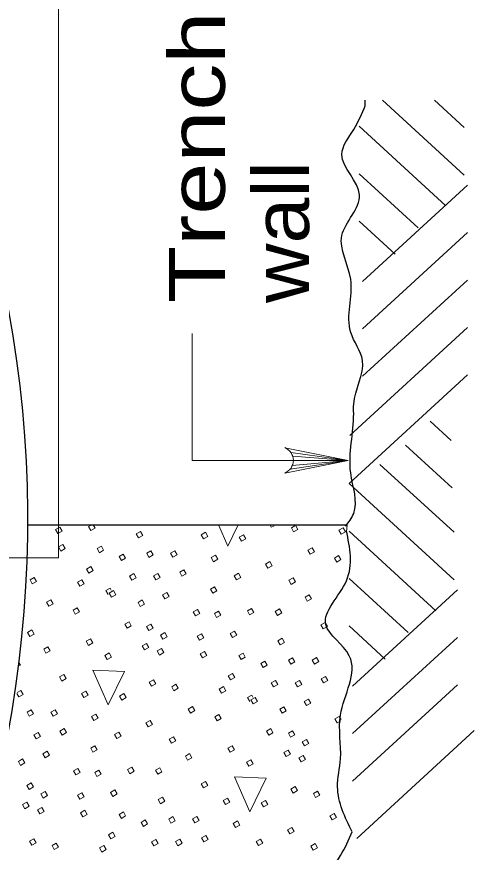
# Model space of a CAD drawing. Extents: x 1170.6 to 1204.6, y 975 to 1019.
# Drawn here: x 1195.183 to 1196.459, y 1001.839 to 1004.167 of the extents above; entities that cross this region are included whole.
import ezdxf

# ---------------------------------------------------------------- set-up
doc = ezdxf.new("R2010")
doc.units = 0
doc.header["$LTSCALE"] = 0.062
doc.linetypes.add('LONG_DASHED', pattern=[7.5, 6, -1.5])
doc.layers.add('1', color=7, linetype='Continuous', lineweight=13)

msp = doc.modelspace()

# ---------------------------------------------------------------- linework, layer by layer
at = {"layer": '1', "lineweight": 25}
for p, q in [((1196.155, 1003.91933), (1196.15475, 1003.93433)), ((1195.21267, 1002.7515), (1196.10433, 1002.7515))]:
    msp.add_line(p, q, dxfattribs=at)
at = {"layer": '1'}
for p, q in [((1196.20317, 1003.93433), (1196.43025, 1003.72617)), ((1196.34742, 1003.93433), (1196.43025, 1003.85842)), ((1196.13792, 1003.862), (1196.37983, 1003.64008)), ((1196.13792, 1003.72983), (1196.30225, 1003.57917)), ((1196.14733, 1003.43), (1196.43967, 1003.698)), ((1196.13792, 1003.59758), (1196.23842, 1003.50533)), ((1196.14733, 1003.29775), (1196.43967, 1003.56575)), ((1196.14733, 1003.16558), (1196.43967, 1003.43358)), ((1196.11175, 1003.00075), (1196.43967, 1003.30142)), ((1196.10992, 1002.86667), (1196.43967, 1003.16917)), ((1196.33558, 1003.04075), (1196.39458, 1002.98658)), ((1196.26725, 1002.97333), (1196.39667, 1002.85467)), ((1195.94717, 1002.95358), (1196.10742, 1002.93117)), ((1195.94533, 1002.90642), (1196.10742, 1002.93117)), ((1195.95142, 1002.91683), (1196.10742, 1002.93117)), ((1195.95267, 1002.9425), (1196.10742, 1002.93117)), ((1195.95425, 1002.93117), (1196.10742, 1002.93117)), ((1196.05575, 1002.93117), (1196.10742, 1002.93117)), ((1196.19575, 1002.92008), (1196.40225, 1002.73083)), ((1196.10992, 1002.86667), (1196.40225, 1002.59858)), ((1195.38358, 1002.74658), (1195.39267, 1002.75183)), ((1195.94892, 1002.74342), (1195.95825, 1002.74875)), ((1196.10225, 1002.73192), (1196.10433, 1002.7515)), ((1196.10992, 1002.73442), (1196.35183, 1002.5125)), ((1196.10992, 1002.60225), (1196.27425, 1002.45158)), ((1195.438, 1002.5575), (1195.43183, 1002.56842)), ((1196.11933, 1002.30242), (1196.41167, 1002.57042)), ((1196.10992, 1002.47), (1196.21042, 1002.37775)), ((1196.11933, 1002.17017), (1196.41167, 1002.43817)), ((1196.11933, 1002.03792), (1196.41167, 1002.306)), ((1195.83283, 1002.25992), (1195.82675, 1002.27083)), ((1196.13092, 1001.87817), (1196.45875, 1002.17883))]:
    msp.add_line(p, q, dxfattribs=at)
for points in [[(1194.2025, 1003.9905), (1194.2025, 1004.66792), (1195.30008, 1004.66792), (1195.30008, 1002.65925), (1194.2025, 1002.65925), (1194.2025, 1002.74183)], [(1196.10742, 1002.93117), (1195.67233, 1002.93117), (1195.67233, 1003.28433)], [(1195.93042, 1002.89583), (1196.10742, 1002.93117), (1195.93042, 1002.96658)], [(1195.39633, 1002.75175), (1195.40175, 1002.74208), (1195.38992, 1002.73542), (1195.38358, 1002.74658)], [(1195.74625, 1002.74992), (1195.77133, 1002.69242), (1195.79917, 1002.74958)], [(1195.90058, 1002.74908), (1195.89275, 1002.74467), (1195.89025, 1002.74917)], [(1195.9615, 1002.74875), (1195.96708, 1002.73892), (1195.95525, 1002.73217), (1195.94892, 1002.74342)], [(1195.43183, 1002.56842), (1195.44375, 1002.57508), (1195.44692, 1002.56942)], [(1195.19017, 1002.36658), (1195.19342, 1002.36092), (1195.18958, 1002.35883)], [(1195.18417, 1002.2845), (1195.1945, 1002.29033), (1195.20083, 1002.27908), (1195.189, 1002.27242), (1195.18392, 1002.28133)], [(1195.82675, 1002.27083), (1195.83858, 1002.2775), (1195.84183, 1002.27183)], [(1196.07042, 1002.21133), (1196.08225, 1002.21808), (1196.08733, 1002.209)], [(1196.08708, 1002.20592), (1196.07675, 1002.20008), (1196.07042, 1002.21133)]]:
    msp.add_lwpolyline(points, dxfattribs=at)
for points in [[(1195.29167, 1002.73883), (1195.3035, 1002.7455), (1195.30983, 1002.73425), (1195.298, 1002.72758)], [(1196.08125, 1002.73683), (1196.09308, 1002.74358), (1196.09942, 1002.73233), (1196.08758, 1002.72558)], [(1195.51625, 1002.72633), (1195.52808, 1002.733), (1195.53442, 1002.72175), (1195.52258, 1002.71508)], [(1195.69758, 1002.72408), (1195.70942, 1002.73083), (1195.71575, 1002.71958), (1195.70392, 1002.71283)], [(1195.80342, 1002.71742), (1195.81525, 1002.72408), (1195.82158, 1002.71283), (1195.80975, 1002.70617)], [(1195.30008, 1002.68992), (1195.31192, 1002.69667), (1195.31825, 1002.68542), (1195.30642, 1002.67867)], [(1195.40733, 1002.68533), (1195.41917, 1002.692), (1195.4255, 1002.68075), (1195.41367, 1002.67408)], [(1195.46858, 1002.66308), (1195.48042, 1002.66975), (1195.48675, 1002.6585), (1195.47492, 1002.65183)], [(1195.54567, 1002.67225), (1195.5575, 1002.67892), (1195.56383, 1002.66767), (1195.552, 1002.661)], [(1195.61233, 1002.67258), (1195.62417, 1002.67925), (1195.63058, 1002.66808), (1195.61867, 1002.66133)], [(1195.995, 1002.68117), (1196.00683, 1002.68792), (1196.01317, 1002.67667), (1196.00133, 1002.66992)], [(1195.72533, 1002.66017), (1195.73717, 1002.66683), (1195.7435, 1002.65558), (1195.73167, 1002.64892)], [(1195.87708, 1002.64233), (1195.88892, 1002.64908), (1195.89525, 1002.63783), (1195.88342, 1002.63108)], [(1196.06883, 1002.65917), (1196.08067, 1002.66592), (1196.087, 1002.65467), (1196.07517, 1002.64792)], [(1195.37792, 1002.6285), (1195.38975, 1002.63525), (1195.39608, 1002.624), (1195.38425, 1002.61733)], [(1195.6375, 1002.61992), (1195.64933, 1002.62667), (1195.65567, 1002.61542), (1195.64383, 1002.60867)], [(1195.22042, 1002.59833), (1195.23225, 1002.605), (1195.23858, 1002.59375), (1195.22675, 1002.58708)], [(1195.498, 1002.609), (1195.50983, 1002.61567), (1195.51617, 1002.60442), (1195.50433, 1002.59775)], [(1195.56467, 1002.60933), (1195.5765, 1002.616), (1195.58283, 1002.60475), (1195.571, 1002.59808)], [(1195.78975, 1002.60983), (1195.80158, 1002.61658), (1195.80792, 1002.60533), (1195.79608, 1002.59858)], [(1195.94208, 1002.59708), (1195.95392, 1002.60375), (1195.96025, 1002.5925), (1195.94842, 1002.58583)], [(1195.35275, 1002.59167), (1195.36458, 1002.59842), (1195.37092, 1002.58717), (1195.35908, 1002.58042)], [(1195.72317, 1002.57217), (1195.735, 1002.57892), (1195.74133, 1002.56767), (1195.7295, 1002.56092)], [(1195.441, 1002.5615), (1195.45283, 1002.56825), (1195.45917, 1002.557), (1195.44733, 1002.55025)], [(1195.58983, 1002.55667), (1195.60167, 1002.56342), (1195.608, 1002.55217), (1195.59617, 1002.54542)], [(1195.987, 1002.55017), (1195.99883, 1002.55683), (1196.00517, 1002.54558), (1195.99333, 1002.53892)], [(1195.2665, 1002.536), (1195.27833, 1002.54275), (1195.28467, 1002.5315), (1195.27283, 1002.52483)], [(1195.5215, 1002.5355), (1195.53333, 1002.54225), (1195.53967, 1002.531), (1195.52783, 1002.52425)], [(1195.34033, 1002.51408), (1195.35217, 1002.52075), (1195.3585, 1002.50958), (1195.34667, 1002.50283)], [(1195.6755, 1002.50892), (1195.68733, 1002.51567), (1195.69367, 1002.50442), (1195.68183, 1002.49767)], [(1195.73425, 1002.5045), (1195.74608, 1002.51125), (1195.75242, 1002.5), (1195.74058, 1002.49325)], [(1195.82617, 1002.51233), (1195.838, 1002.519), (1195.84433, 1002.50775), (1195.8325, 1002.50108)], [(1195.90367, 1002.51058), (1195.9155, 1002.51733), (1195.92192, 1002.50608), (1195.91, 1002.49933)], [(1195.4845, 1002.47467), (1195.49633, 1002.48142), (1195.50267, 1002.47017), (1195.49083, 1002.46342)], [(1195.5455, 1002.46858), (1195.55733, 1002.47525), (1195.56367, 1002.46408), (1195.55183, 1002.45733)], [(1196.03142, 1002.47292), (1196.04325, 1002.47958), (1196.04958, 1002.46833), (1196.03775, 1002.46167)], [(1195.21358, 1002.45192), (1195.22542, 1002.45867), (1195.23175, 1002.44742), (1195.21992, 1002.44067)], [(1195.58442, 1002.44458), (1195.59625, 1002.45125), (1195.60267, 1002.44), (1195.59075, 1002.43333)], [(1195.68658, 1002.44125), (1195.69842, 1002.44792), (1195.70475, 1002.43675), (1195.69292, 1002.43)], [(1195.7785, 1002.44908), (1195.79033, 1002.45575), (1195.79667, 1002.4445), (1195.78483, 1002.43783)], [(1195.37692, 1002.42717), (1195.38875, 1002.43383), (1195.39517, 1002.42267), (1195.38325, 1002.41592)], [(1195.53333, 1002.41475), (1195.54517, 1002.4215), (1195.5515, 1002.41025), (1195.53967, 1002.4035)], [(1195.91117, 1002.42875), (1195.923, 1002.4355), (1195.92933, 1002.42425), (1195.9175, 1002.4175)], [(1195.2585, 1002.405), (1195.27033, 1002.41175), (1195.27667, 1002.4005), (1195.26483, 1002.39375)], [(1195.429, 1002.38792), (1195.44083, 1002.39467), (1195.44717, 1002.38342), (1195.43533, 1002.37675)], [(1195.575, 1002.40025), (1195.58683, 1002.40692), (1195.59325, 1002.39567), (1195.58133, 1002.389)], [(1195.695, 1002.39233), (1195.70683, 1002.39908), (1195.71317, 1002.38783), (1195.70133, 1002.38108)], [(1195.80225, 1002.38775), (1195.81408, 1002.3945), (1195.82042, 1002.38325), (1195.80858, 1002.3765)], [(1195.8635, 1002.3655), (1195.87533, 1002.37217), (1195.88167, 1002.361), (1195.86983, 1002.35425)], [(1195.94058, 1002.37467), (1195.95242, 1002.38142), (1195.95875, 1002.37017), (1195.94692, 1002.36342)], [(1196.00725, 1002.375), (1196.01908, 1002.38167), (1196.02542, 1002.3705), (1196.01358, 1002.36375)], [(1195.39517, 1002.34717), (1195.43775, 1002.24975), (1195.48333, 1002.34342)], [(1195.30292, 1002.32775), (1195.31475, 1002.3345), (1195.32108, 1002.32325), (1195.30925, 1002.3165)], [(1195.55283, 1002.31317), (1195.56467, 1002.31992), (1195.571, 1002.30867), (1195.55917, 1002.30192)], [(1195.77283, 1002.331), (1195.78467, 1002.33767), (1195.791, 1002.32642), (1195.77917, 1002.31975)], [(1196.03233, 1002.32242), (1196.04425, 1002.32908), (1196.05058, 1002.31783), (1196.03867, 1002.31117)], [(1195.61533, 1002.30075), (1195.62717, 1002.30742), (1195.6335, 1002.29625), (1195.62167, 1002.2895)], [(1195.74767, 1002.29417), (1195.7595, 1002.30083), (1195.76583, 1002.28958), (1195.754, 1002.28292)], [(1195.89292, 1002.31142), (1195.90475, 1002.31808), (1195.91108, 1002.30683), (1195.89925, 1002.30017)], [(1195.95958, 1002.31175), (1195.97142, 1002.31842), (1195.97775, 1002.30725), (1195.96592, 1002.3005)], [(1195.364, 1002.28142), (1195.37583, 1002.28808), (1195.38217, 1002.27692), (1195.37033, 1002.27017)], [(1195.46983, 1002.27467), (1195.48167, 1002.28142), (1195.488, 1002.27017), (1195.47617, 1002.26342)], [(1195.83592, 1002.26392), (1195.84775, 1002.27067), (1195.85408, 1002.25942), (1195.84225, 1002.25267)], [(1195.98467, 1002.25908), (1195.99658, 1002.26583), (1196.00292, 1002.25458), (1195.991, 1002.24792)], [(1195.21208, 1002.2295), (1195.22392, 1002.23625), (1195.23025, 1002.225), (1195.21842, 1002.21825)], [(1195.27875, 1002.22983), (1195.29058, 1002.23658), (1195.29692, 1002.22533), (1195.28508, 1002.21858)], [(1195.66142, 1002.23842), (1195.67325, 1002.24517), (1195.67958, 1002.23392), (1195.66775, 1002.22725)], [(1195.91633, 1002.23792), (1195.92825, 1002.24467), (1195.93458, 1002.23342), (1195.92275, 1002.22667)], [(1195.39175, 1002.21742), (1195.40358, 1002.22417), (1195.40992, 1002.21292), (1195.39808, 1002.20617)], [(1195.5435, 1002.19967), (1195.55533, 1002.20633), (1195.56167, 1002.19508), (1195.54983, 1002.18842)], [(1195.73525, 1002.2165), (1195.74708, 1002.22325), (1195.75342, 1002.212), (1195.74158, 1002.20525)], [(1195.30383, 1002.17725), (1195.31575, 1002.184), (1195.32208, 1002.17275), (1195.31025, 1002.166)], [(1195.87942, 1002.17708), (1195.89125, 1002.18383), (1195.89758, 1002.17258), (1195.88575, 1002.16583)], [(1195.23108, 1002.16658), (1195.24292, 1002.17333), (1195.24925, 1002.16208), (1195.23742, 1002.15533)], [(1195.45608, 1002.16717), (1195.468, 1002.17383), (1195.47433, 1002.16258), (1195.4625, 1002.15592)], [(1195.60842, 1002.15433), (1195.62025, 1002.16108), (1195.62658, 1002.14983), (1195.61475, 1002.14308)], [(1195.94042, 1002.171), (1195.95225, 1002.17775), (1195.95858, 1002.1665), (1195.94675, 1002.15975)], [(1195.38958, 1002.1295), (1195.40142, 1002.13617), (1195.40775, 1002.12492), (1195.39592, 1002.11825)], [(1195.77183, 1002.12958), (1195.78367, 1002.13625), (1195.79, 1002.12508), (1195.77817, 1002.11833)], [(1195.97933, 1002.147), (1195.99117, 1002.15367), (1195.9975, 1002.14242), (1195.98567, 1002.13575)], [(1195.25617, 1002.114), (1195.26808, 1002.12075), (1195.27442, 1002.1095), (1195.26258, 1002.10275)], [(1195.65342, 1002.10742), (1195.66525, 1002.11417), (1195.67158, 1002.10292), (1195.65975, 1002.09617)], [(1195.92825, 1002.11717), (1195.94008, 1002.12392), (1195.94642, 1002.11267), (1195.93458, 1002.10592)], [(1195.18792, 1002.09275), (1195.19975, 1002.0995), (1195.20608, 1002.08825), (1195.19425, 1002.08158)], [(1195.82383, 1002.09033), (1195.83567, 1002.09708), (1195.842, 1002.08583), (1195.83017, 1002.07917)], [(1195.96992, 1002.10267), (1195.98175, 1002.10933), (1195.98808, 1002.09808), (1195.97625, 1002.09142)], [(1195.34192, 1002.06617), (1195.35375, 1002.07292), (1195.36008, 1002.06167), (1195.34825, 1002.055)], [(1195.40058, 1002.06183), (1195.4125, 1002.0685), (1195.41883, 1002.05725), (1195.407, 1002.05058)], [(1195.4925, 1002.06958), (1195.50442, 1002.07633), (1195.51075, 1002.06508), (1195.49892, 1002.05833)], [(1195.57008, 1002.06792), (1195.58192, 1002.07458), (1195.58825, 1002.06342), (1195.57642, 1002.05667)], [(1195.79008, 1002.04958), (1195.83267, 1001.95217), (1195.87825, 1002.04583)], [(1195.21192, 1002.02583), (1195.22375, 1002.03258), (1195.23008, 1002.02133), (1195.21825, 1002.01458)], [(1195.69775, 1002.03017), (1195.70967, 1002.03692), (1195.716, 1002.02567), (1195.70417, 1002.01892)], [(1195.94775, 1002.01558), (1195.95958, 1002.02233), (1195.96592, 1002.01108), (1195.95408, 1002.00433)], [(1195.25083, 1002.00183), (1195.26267, 1002.00858), (1195.269, 1001.99733), (1195.25717, 1001.99058)], [(1195.35292, 1001.9985), (1195.36483, 1002.00525), (1195.37117, 1001.994), (1195.35925, 1001.98733)], [(1195.44483, 1002.00633), (1195.45675, 1002.01308), (1195.46308, 1002.00183), (1195.45125, 1001.99508)], [(1196.01017, 1002.00317), (1196.022, 1002.00983), (1196.02833, 1001.99867), (1196.0165, 1001.99192)], [(1195.19975, 1001.97208), (1195.21158, 1001.97875), (1195.21792, 1001.9675), (1195.20608, 1001.96083)], [(1195.57758, 1001.986), (1195.58942, 1001.99275), (1195.59575, 1001.9815), (1195.58392, 1001.97483)], [(1195.75892, 1001.98383), (1195.77075, 1001.99058), (1195.77708, 1001.97933), (1195.76525, 1001.97258)], [(1195.86467, 1001.97708), (1195.8765, 1001.98383), (1195.88283, 1001.97258), (1195.871, 1001.96583)], [(1195.24142, 1001.9575), (1195.25325, 1001.96425), (1195.25958, 1001.953), (1195.24775, 1001.94625)], [(1195.36133, 1001.94967), (1195.37317, 1001.95633), (1195.37958, 1001.94508), (1195.36775, 1001.93842)], [(1195.46867, 1001.94508), (1195.4805, 1001.95175), (1195.48683, 1001.9405), (1195.475, 1001.93383)], [(1196.05625, 1001.94092), (1196.06817, 1001.94758), (1196.0745, 1001.93633), (1196.06267, 1001.92967)], [(1195.52992, 1001.92275), (1195.54175, 1001.9295), (1195.54808, 1001.91825), (1195.53625, 1001.9115)], [(1195.607, 1001.93192), (1195.61883, 1001.93867), (1195.62517, 1001.92742), (1195.61333, 1001.92075)], [(1195.67367, 1001.93233), (1195.6855, 1001.939), (1195.69183, 1001.92775), (1195.68, 1001.92108)], [(1195.78658, 1001.91983), (1195.7985, 1001.92658), (1195.80483, 1001.91533), (1195.79292, 1001.90858)], [(1195.93842, 1001.90208), (1195.95025, 1001.90875), (1195.95658, 1001.89758), (1195.94475, 1001.89083)], [(1195.43925, 1001.88825), (1195.45108, 1001.895), (1195.45742, 1001.88375), (1195.44558, 1001.877)], [(1195.69875, 1001.87967), (1195.71058, 1001.88642), (1195.71692, 1001.87517), (1195.70508, 1001.86842)], [(1195.21925, 1001.8705), (1195.23108, 1001.87717), (1195.23742, 1001.866), (1195.22558, 1001.85925)], [(1195.28167, 1001.858), (1195.2935, 1001.86475), (1195.29992, 1001.8535), (1195.288, 1001.84675)], [(1195.41408, 1001.85142), (1195.42592, 1001.85817), (1195.43225, 1001.84692), (1195.42042, 1001.84017)], [(1195.55933, 1001.86867), (1195.57117, 1001.87542), (1195.5775, 1001.86417), (1195.56567, 1001.85742)], [(1195.626, 1001.869), (1195.63783, 1001.87575), (1195.64417, 1001.8645), (1195.63233, 1001.85775)], [(1195.851, 1001.86958), (1195.86283, 1001.87625), (1195.86917, 1001.865), (1195.85733, 1001.85833)], [(1196.00333, 1001.85675), (1196.01517, 1001.8635), (1196.0215, 1001.85225), (1196.00967, 1001.8455)]]:
    msp.add_lwpolyline(points, close=True, dxfattribs=at)
msp.add_arc((1195.91615, 1002.93123), 0.0382, 292.08605, 67.91218, dxfattribs=at)
at = {"layer": '1', "lineweight": 25}
msp.add_ellipse((1192.33349, 1002.76462), major_axis=(0, 3.04986), ratio=0.944544, start_param=3.7685949, end_param=5.2606747, dxfattribs=at)
at = {"layer": '1', "linetype": 'LONG_DASHED'}
msp.add_ellipse((1192.32486, 1002.77617), major_axis=(0, 2.93373), ratio=0.944544, start_param=4.2344755, end_param=5.1344826, dxfattribs=at)
at = {"layer": '1', "lineweight": 25}
for points in [[(1196.1, 1002.74783), (1196.12258, 1002.78308), (1196.11433, 1002.89625), (1196.12258, 1003.0615), (1196.12258, 1003.08767), (1196.14717, 1003.2095), (1196.11433, 1003.28783), (1196.11433, 1003.43575), (1196.08967, 1003.5575), (1196.139, 1003.67067), (1196.08967, 1003.78375), (1196.12258, 1003.85342), (1196.155, 1003.91933)], [(1196.11825, 1001.89608), (1196.07767, 1002.02158), (1196.08583, 1002.09983), (1196.08583, 1002.22167), (1196.11042, 1002.387), (1196.04475, 1002.474), (1196.10225, 1002.59583), (1196.10225, 1002.73508)], [(1196.06508, 1001.47525), (1196.05292, 1001.53425), (1196.10225, 1001.64742), (1196.05292, 1001.7605), (1196.08583, 1001.83017), (1196.11825, 1001.89608)]]:
    msp.add_spline(points, degree=3, dxfattribs=at)

# ---------------------------------------------------------------- texts
at = {"layer": '1'}
for s, width, p in [('Trench', 1.25, (1195.7635, 1003.36967)), ('wall', 1.1, (1195.99817, 1003.36967))]:
    msp.add_text(s, height=0.156, rotation=90, dxfattribs=dict(at, width=width)).set_placement(p)

doc.saveas('drawing.dxf')
